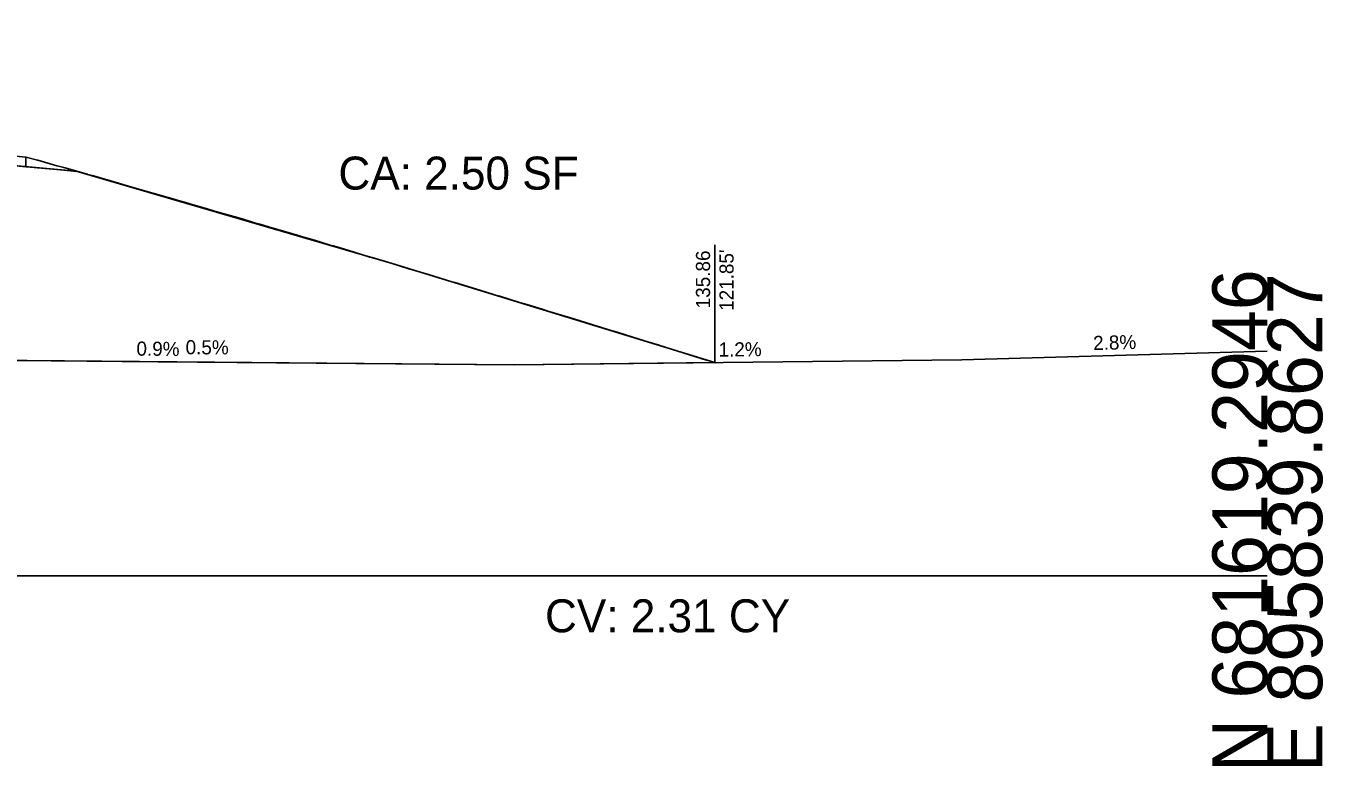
# Model space of a CAD drawing. Extents: x -26 to 4303, y -13 to 10775.
# Drawn here: x 3236.8 to 3302.8, y 4990.3 to 5028 of the extents above; entities that cross this region are included whole.
import ezdxf

# ---------------------------------------------------------------- set-up
doc = ezdxf.new("R2010")
doc.units = 0
for name, color, linetype in [('DTM_X_GROUND', 7, 'Continuous'), ('X_PROFILES_1', 7, 'Continuous'), ('XS_CELL', 7, 'Continuous'), ('XS_M_SHAPES_EARTHWORK', 7, 'Continuous'), ('XS_P_DR_GRAVEL', 7, 'Continuous'), ('XS_P_GROUND', 7, 'Continuous'), ('XS_P_TX_CLEARZONE', 7, 'Continuous'), ('XS_P_TX_FS_BS', 7, 'Continuous'), ('XS_SHEET_EW_TX_AREA', 7, 'Continuous'), ('XS_SHEET_EW_TX_VOLUME', 7, 'Continuous')]:
    doc.layers.add(name, color=color, linetype=linetype)

msp = doc.modelspace()

# ---------------------------------------------------------------- linework, layer by layer
at = {"layer": 'DTM_X_GROUND'}
msp.add_lwpolyline([(3121.043, 5028.008), (3124.888, 5027.357), (3125.792, 5027.191), (3133.123, 5022.647), (3142.048, 5017.046), (3149.924, 5014.592), (3150.011, 5014.564), (3156.484, 5013.493), (3157.461, 5013.398), (3177.004, 5012.157), (3200.167, 5011.663), (3206.976, 5011.327), (3212.719, 5011.146), (3225.338, 5011.067), (3261.632, 5010.739), (3284.436, 5011.007), (3300, 5011.444)], dxfattribs=at)
at = {"layer": 'XS_CELL'}
msp.add_line((3150, 5000), (3300, 5000), dxfattribs=at)
at = {"layer": 'XS_P_DR_GRAVEL'}
for points in [[(3236.076, 5020.893), (3236.758, 5020.831), (3236.758, 5021.331), (3236.076, 5021.393)], [(3236.758, 5020.831), (3236.827, 5020.825), (3237.343, 5020.78), (3238.333, 5020.691), (3238.683, 5020.663), (3239.358, 5020.602)]]:
    msp.add_lwpolyline(points, dxfattribs=at)
at = {"layer": 'XS_P_GROUND'}
msp.add_lwpolyline([(3236.758, 5021.331), (3236.827, 5021.312), (3236.829, 5021.312), (3237.343, 5021.169), (3237.361, 5021.165), (3238.333, 5020.89), (3238.349, 5020.886), (3238.683, 5020.795), (3238.754, 5020.776), (3239.883, 5020.452), (3239.899, 5020.448), (3240.057, 5020.407), (3240.202, 5020.368), (3241.468, 5020), (3241.478, 5019.997), (3241.48, 5019.997), (3241.692, 5019.939), (3242.919, 5019.579), (3242.939, 5019.573), (3243.029, 5019.547), (3243.299, 5019.473), (3244.411, 5019.149), (3244.508, 5019.123), (3244.829, 5019.032), (3245.108, 5018.954), (3245.948, 5018.704), (3246.097, 5018.662), (3246.483, 5018.544), (3246.797, 5018.457), (3247.531, 5018.242), (3247.82, 5018.161), (3248.408, 5017.985), (3248.676, 5017.909), (3249.163, 5017.763), (3249.595, 5017.64), (3250.295, 5017.427), (3250.522, 5017.363), (3250.849, 5017.266), (3251.459, 5017.089), (3252.252, 5016.845), (3252.409, 5016.801), (3252.591, 5016.748), (3253.422, 5016.504), (3254.285, 5016.237), (3254.337, 5016.224), (3254.392, 5016.21), (3255.413, 5015.905), (3256.258, 5015.638), (3256.318, 5015.622), (3256.399, 5015.601), (3257.484, 5015.277), (3258.191, 5015.055), (3258.452, 5014.979), (3258.602, 5014.934), (3259.667, 5014.614), (3260.197, 5014.446), (3260.686, 5014.301), (3260.899, 5014.235), (3261.909, 5013.929), (3262.281, 5013.811), (3263.057, 5013.577), (3263.298, 5013.501), (3264.212, 5013.223), (3264.448, 5013.148), (3265.58, 5012.801), (3265.808, 5012.729), (3266.579, 5012.494), (3266.704, 5012.454), (3268.274, 5011.969), (3268.438, 5011.916), (3269.01, 5011.742), (3269.056, 5011.728), (3271.161, 5011.071), (3271.199, 5011.059), (3271.51, 5010.967), (3271.513, 5010.966), (3271.851, 5010.859)], dxfattribs=at)
at = {"layer": 'XS_P_TX_CLEARZONE'}
msp.add_line((3271.851, 5010.859), (3271.851, 5016.859), dxfattribs=at)
msp.add_line((3271.851, 5010.859), (3271.851, 5016.859), dxfattribs=at)
msp.add_line((3271.851, 5010.859), (3271.851, 5016.859), dxfattribs=at)
at = {"layer": 'XS_SHEET_EW_TX_AREA'}
msp.add_lwpolyline([(3271.851, 5010.859), (3261.632, 5010.739), (3243.485, 5010.903), (3225.338, 5011.067), (3220.13, 5011.099), (3180, 5024.475), (3171.412, 5026.649), (3178, 5026.242), (3178, 5026.742), (3192.941, 5025.322), (3192.941, 5024.822), (3239.318, 5020.614), (3255.413, 5015.905)], close=True, dxfattribs=at)

# ---------------------------------------------------------------- texts
at = {"layer": 'X_PROFILES_1'}
msp.add_text('X', height=0.12, dxfattribs=at).set_placement((3271.812, 5010.799))
at = {"layer": 'XS_CELL'}
for s, p in [('N 681619.2946', (3300, 4990)), ('E 895839.8627', (3302.8, 4990))]:
    msp.add_text(s, height=2.8, rotation=90, dxfattribs=at).set_placement(p)
at = {"layer": 'XS_M_SHAPES_EARTHWORK'}
msp.add_text('CV: 2.31 CY', height=1.68, dxfattribs=at).set_placement((3263.203, 4997.12))
at = {"layer": 'XS_P_TX_CLEARZONE'}
for s, p in [('135.86', (3271.611, 5013.624)), ('135.86', (3271.611, 5013.624)), ('135.86', (3271.611, 5013.624)), ("121.85'", (3272.811, 5013.493)), ("121.85'", (3272.811, 5013.493)), ("121.85'", (3272.811, 5013.493))]:
    msp.add_text(s, height=0.72, rotation=90, dxfattribs=at).set_placement(p)
at = {"layer": 'XS_P_TX_FS_BS'}
for s, rotation, p in [('2.8%', 1.61055, (3291.136, 5011.495)), ('0.9%', 359.48288, (3242.386, 5011.213)), ('0.5%', 359.73392, (3244.89, 5011.284)), ('1.2%', 0.67202, (3272.047, 5011.161))]:
    msp.add_text(s, height=0.72, rotation=rotation, dxfattribs=at).set_placement(p)
at = {"layer": 'XS_SHEET_EW_TX_VOLUME'}
msp.add_text('CA: 2.50 SF', height=1.68, dxfattribs=at).set_placement((3252.677, 5019.672))

doc.saveas('drawing.dxf')
